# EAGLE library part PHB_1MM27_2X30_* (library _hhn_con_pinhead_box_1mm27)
Pin Header Box-Type, 1.27mm/0.5"/50mil Pitch, 2x30 Circuits Note: see library description for an important note about THT-version
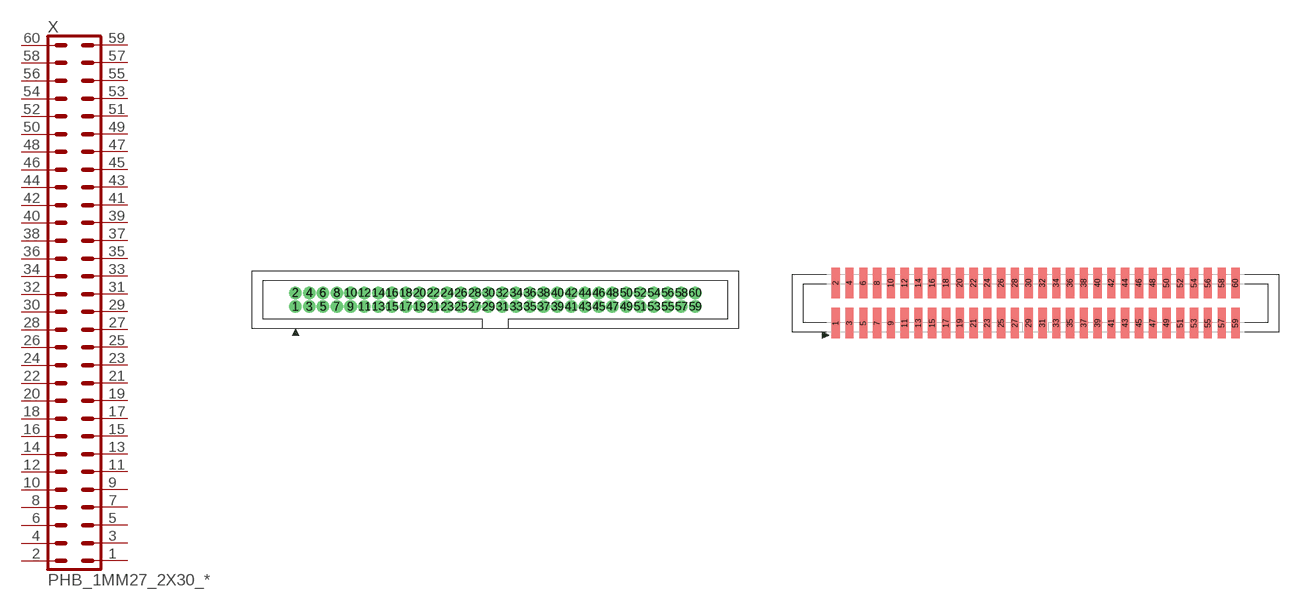
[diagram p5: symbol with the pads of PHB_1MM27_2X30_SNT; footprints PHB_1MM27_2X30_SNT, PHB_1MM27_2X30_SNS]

Designator prefix X

## PHB_1MM27_2X30_SNT  [PHB_1MM27_2X30_SNT]
1  1  pas
2  2  pas
3  3  pas
4  4  pas
5  5  pas
6  6  pas
7  7  pas
8  8  pas
9  9  pas
10  10  pas
11  11  pas
12  12  pas
13  13  pas
14  14  pas
15  15  pas
16  16  pas
17  17  pas
18  18  pas
19  19  pas
20  20  pas
21  21  pas
22  22  pas
23  23  pas
24  24  pas
25  25  pas
26  26  pas
27  27  pas
28  28  pas
29  29  pas
30  30  pas
31  31  pas
32  32  pas
33  33  pas
34  34  pas
35  35  pas
36  36  pas
37  37  pas
38  38  pas
39  39  pas
40  40  pas
41  41  pas
42  42  pas
43  43  pas
44  44  pas
45  45  pas
46  46  pas
47  47  pas
48  48  pas
49  49  pas
50  50  pas
51  51  pas
52  52  pas
53  53  pas
54  54  pas
55  55  pas
56  56  pas
57  57  pas
58  58  pas
59  59  pas
60  60  pas

## PHB_1MM27_2X30_SNS  [PHB_1MM27_2X30_SNS]
Pads as for PHB_1MM27_2X30_SNT

## Footprint PHB_1MM27_2X30_SNT (pad centres in mm)
Pin Header Box-Type, 1.27mm Pitch, 2x30 circuits, Straight, No Locking, THT Important Note: Diameter in this lbr is set to a specific value (NOT 'auto' = 0), this is ignored by actual eagle versions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
drill 0.65 pad 1 round: 1 -18.415,-0.635; 2 -18.415,0.635; 3 -17.145,-0.635; 4 -17.145,0.635; 5 -15.875,-0.635; 6 -15.875,0.635; 7 -14.605,-0.635; 8 -14.605,0.635; 9 -13.335,-0.635; 10 -13.335,0.635; 11 -12.065,-0.635; 12 -12.065,0.635; 13 -10.795,-0.635; 14 -10.795,0.635; 15 -9.525,-0.635; 16 -9.525,0.635; 17 -8.255,-0.635; 18 -8.255,0.635; 19 -6.985,-0.635; 20 -6.985,0.635; 21 -5.715,-0.635; 22 -5.715,0.635; 23 -4.445,-0.635; 24 -4.445,0.635; 25 -3.175,-0.635; 26 -3.175,0.635; 27 -1.905,-0.635; 28 -1.905,0.635; 29 -0.635,-0.635; 30 -0.635,0.635; 31 0.635,-0.635; 32 0.635,0.635; 33 1.905,-0.635; 34 1.905,0.635; 35 3.175,-0.635; 36 3.175,0.635; 37 4.445,-0.635; 38 4.445,0.635; 39 5.715,-0.635; 40 5.715,0.635; 41 6.985,-0.635; 42 6.985,0.635; 43 8.255,-0.635; 44 8.255,0.635; 45 9.525,-0.635; 46 9.525,0.635; 47 10.795,-0.635; 48 10.795,0.635; 49 12.065,-0.635; 50 12.065,0.635; 51 13.335,-0.635; 52 13.335,0.635; 53 14.605,-0.635; 54 14.605,0.635; 55 15.875,-0.635; 56 15.875,0.635; 57 17.145,-0.635; 58 17.145,0.635; 59 18.415,-0.635; 60 18.415,0.635

## Footprint PHB_1MM27_2X30_SNS (pad centres in mm)
Pin Header Box-Type, 1.27mm Pitch, 2x30 circuits, Straight, No Locking, SMT
smd 0.76 x 2.8: 1 -18.415,-1.85; 2 -18.415,1.85; 3 -17.145,-1.85; 4 -17.145,1.85; 5 -15.875,-1.85; 6 -15.875,1.85; 7 -14.605,-1.85; 8 -14.605,1.85; 9 -13.335,-1.85; 10 -13.335,1.85; 11 -12.065,-1.85; 12 -12.065,1.85; 13 -10.795,-1.85; 14 -10.795,1.85; 15 -9.525,-1.85; 16 -9.525,1.85; 17 -8.255,-1.85; 18 -8.255,1.85; 19 -6.985,-1.85; 20 -6.985,1.85; 21 -5.715,-1.85; 22 -5.715,1.85; 23 -4.445,-1.85; 24 -4.445,1.85; 25 -3.175,-1.85; 26 -3.175,1.85; 27 -1.905,-1.85; 28 -1.905,1.85; 29 -0.635,-1.85; 30 -0.635,1.85; 31 0.635,-1.85; 32 0.635,1.85; 33 1.905,-1.85; 34 1.905,1.85; 35 3.175,-1.85; 36 3.175,1.85; 37 4.445,-1.85; 38 4.445,1.85; 39 5.715,-1.85; 40 5.715,1.85; 41 6.985,-1.85; 42 6.985,1.85; 43 8.255,-1.85; 44 8.255,1.85; 45 9.525,-1.85; 46 9.525,1.85; 47 10.795,-1.85; 48 10.795,1.85; 49 12.065,-1.85; 50 12.065,1.85; 51 13.335,-1.85; 52 13.335,1.85; 53 14.605,-1.85; 54 14.605,1.85; 55 15.875,-1.85; 56 15.875,1.85; 57 17.145,-1.85; 58 17.145,1.85; 59 18.415,-1.85; 60 18.415,1.85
